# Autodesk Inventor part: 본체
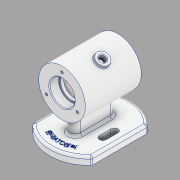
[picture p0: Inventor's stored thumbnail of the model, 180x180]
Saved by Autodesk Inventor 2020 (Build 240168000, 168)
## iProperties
Created: 2022-02
Part Number: 본체
Material: 알루미늄 6061
Document SubType Name: Modeling
Designer: 602-11
Mass: 495.267 g
Surface Area: 489.781 cm^2
Volume: 183.432 cm^3
Density: 2.7 g/cm^3
Appearance: 알루미늄 - 평지
Author: 602-11
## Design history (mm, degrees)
sketch "스케치1"
  geometry: C1 r 30 at (0, 0); 1 further point
  constraints: 1 centre point, 1 coincident
  dimensions: "d0" = 60 diameter of C1
extrude "돌출1" new body sketch "스케치1" stored distance "d1" = 72; taper "d2" = 0 deg
sketch "스케치2"
  geometry: L1 (30, 36)-(-30, 36) reference; L2 (0, 36)-(0, -36); L3 (-30, -36)-(30, -36) reference; L4 (16, 36)-(16, 24); L5 (16, 24)-(14, 24); L6 (14, 24)-(14, 20); L7 (14, 20)-(25, 20); L8 (25, 20)-(25, -20); L9 (25, -20)-(14, -20); L10 (14, -20)-(14, -24); L11 (14, -24)-(16, -24); L12 (16, -24)-(16, -36); 1 further point
  constraints: 20 end point, 6 perpendicular, 6 point on line, 2 midpoint, 1 vertical
  dimensions: "d3" = 12 distance of L4.start L4.end; "d4" = 12 distance of L11.end L12.end; "d5" = 40 distance of L7.end L8.end; "d6" = 50 diameter of L8 L2; "d7" = 28 diameter of L10 L2; "d8" = 32 diameter of L12 L2; "d9" = 4 distance of L5.end L6.end
revolve "회전1" sketch "스케치2" stored, may be unused: angle "d10" = 90 deg
node "작업 평면1"
sketch "스케치3" dims "d12" = 104
  geometry: L1 (-38, -35.496)-(38, -35.496); L2 (38, -35.496)-(38, 35.496); L3 (38, 35.496)-(-38, 35.496); L4 (-38, 35.496)-(-38, -35.496); L5 (-38, -35.496)-(38, 35.496); L6 (38, -35.496)-(-38, 35.496); 5 further points
  constraints: 12 end point, 2 midpoint, 2 parallel, 1 coincident, 1 horizontal, 1 perpendicular, 3 other
  dimensions: "d13" = 76 distance of L2.end L3.end
extrude "돌출2" join sketch "스케치3" distance "d14" = 10; taper "d15" = 0 deg
sketch "스케치4"
  geometry: L1 (0, 19)-(0, -19); L2 (-7, 19)-(-7, -19); L3 (7, -19)-(7, 19); A1 r 7 centre (0, 19) between (7, 19) and (-7, 19); A2 r 7 centre (0, -19) between (-7, -19) and (7, -19); 1 further point
  constraints: 8 end point, 4 point on circle, 4 tangent, 2 centre point, 1 midpoint, 1 parallel, 1 vertical
  dimensions: "d16" = 14 diameter of A2; "d17" = 38 distance of L1.end L1.start
extrude "돌출3" join sketch "스케치4" stored distance "d18" = 10; taper "d19" = 0 deg
sketch "스케치5"
  geometry: L1 (0, 0)-(-24, 0); L2 (-24, -7.5)-(-24, 7.5); L3 (-28.5, -7.5)-(-28.5, 7.5); L4 (-19.5, 7.5)-(-19.5, -7.5); A1 r 4.5 centre (-24, -7.5) between (-28.5, -7.5) and (-19.5, -7.5); A2 r 4.5 centre (-24, 7.5) between (-19.5, 7.5) and (-28.5, 7.5)
  constraints: 10 end point, 4 point on circle, 4 tangent, 2 centre point, 1 horizontal, 1 midpoint, 1 parallel, 1 vertical
  dimensions: "d20" = 24 distance of L1.start L1.end; "d21" = 4.5 radius of A2; "d22" = 15 distance of L2.start L2.end
extrude "돌출4" cut sketch "스케치5" extent not by distance; stored distance "d23" = 74.798; taper "d24" = 0 deg
sketch "스케치6" dims "d25" = 46
  geometry: L1 (0, 0)-(0, 23); 2 further points
  constraints: 2 coincident, 2 end point, 1 vertical, 1 vertical alignment, 2 other
hole "구멍1" sketch "스케치6" at (0, 23) diameter "d26" = 3.242; stored, may be unused: countersink angle "d30" = 90 deg, drill point angle "d32" = 118 deg; dims "d27" = 8, "d28" = 4, "d29" = 2, "d31" = 10
fillet "모깎기1" dims "d36" = 3
fillet "모깎기2" dims "d37" = 3
fillet "모깎기3" dims "d38" = 3
sketch "스케치7"
  geometry: C1 r 42.5 at (0, 0); 1 further point
  constraints: 1 centre point, 1 coincident, 1 other
  dimensions: "d39" = 85 diameter of C1
feature "엠보싱1" sketch "스케치7" dims "d12" = 104, "d40" = 0.5, "d41" = 0
sketch "스케치8"
  geometry: L1 (0, 0)-(0, 30); L2 (0, 0)-(15, 25.981); L3 (15, 25.981)-(16.5, 28.579); L4 (16.5, 28.579)-(9.572, 32.579); L5 (9.572, 32.579)-(7.529, 29.04); 3 further points
  constraints: 10 end point, 1 vertical, 2 other
  dimensions: "d61" = 16 diameter of L5 L3; "d62" = 33 distance of point (0, 0) L3.end
revolve "회전2" sketch "스케치8" stored, may be unused: angle "d46" = 90 deg
chamfer "모따기1" distance "d56" = 1; stored, may be unused: second distance "d57" = 2, angle "d58" = 45 deg
fillet "모깎기6" dims "d59" = 0.3
fillet "모깎기7" dims "d60" = 3
sketch "스케치10"
  geometry: C1 r 8 at (0, 0) reference; 1 further point
hole "구멍3" sketch "스케치10" at (0, 0) diameter "d63" = 8; stored, may be unused: countersink angle "d67" = 90 deg, drill point angle "d69" = 0 deg; dims "d64" = 8, "d65" = 4, "d66" = 2, "d68" = 10
fillet "모깎기8" dims "d70" = 1
node "솔리드1"
mirror "미러1"
pattern_circular "원형 패턴1" dims angle "d34" = 360 deg
mirror "미러2"
node "투영된 루프2"
feature "A9D066F2-1C7D-4E18-AEED-F7BC21143FA4" dims "d63" = 8, "d64" = 8, "d65" = 4, "d66" = 2, "d67" = 90 deg, "d68" = 10, "d69" = 0
other parameters: "d11" = -62
